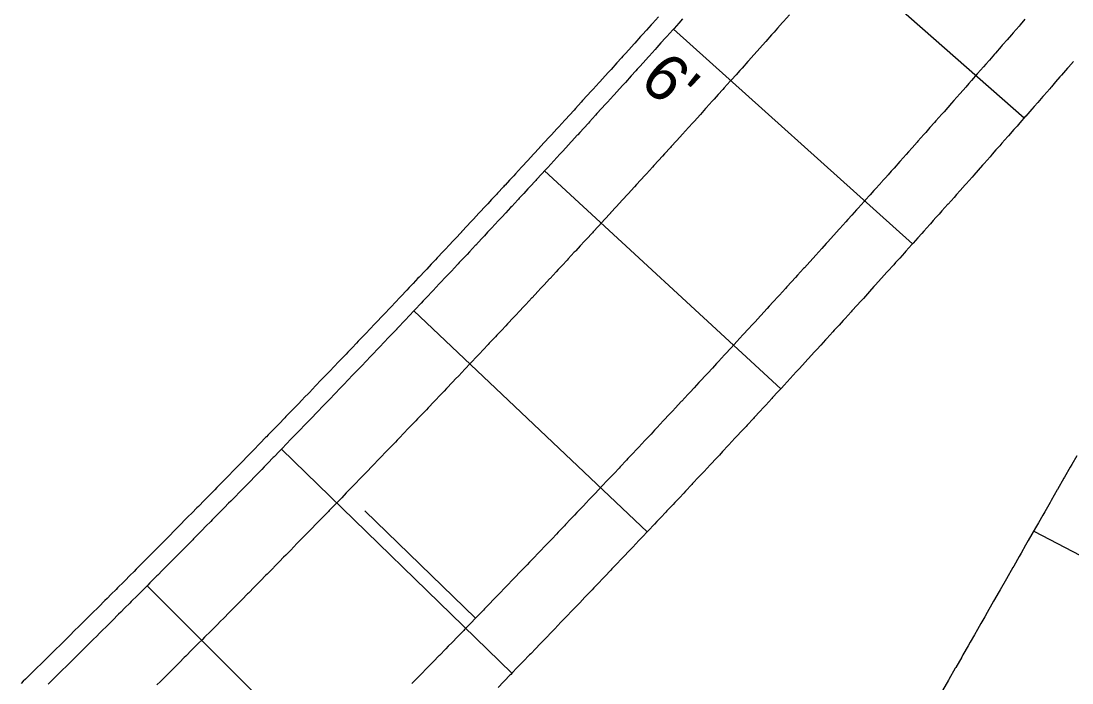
# Model space of a CAD drawing. Extents: x 2145147 to 2158018, y 137519 to 148068.
# Drawn here: x 2150345.5 to 2150427.2, y 143802 to 143853.5 of the extents above; entities that cross this region are included whole.
import ezdxf

# ---------------------------------------------------------------- set-up
doc = ezdxf.new("R2010")
doc.units = 0
for name, color, linetype in [('PR_Align_Ramp_F', 7, 'Continuous'), ('PR_Dimensions', 7, 'Continuous'), ('PR_Joint_Contraction', 7, 'Continuous'), ('PR_Joint_Long', 7, 'Continuous'), ('PR_Road_Concrete', 7, 'Continuous')]:
    doc.layers.add(name, color=color, linetype=linetype)

msp = doc.modelspace()

# ---------------------------------------------------------------- linework, layer by layer
at = {"layer": 'PR_Align_Ramp_F'}
msp.add_lwpolyline([(2150380.826, 143807.064), (2150372.211, 143815.417)], dxfattribs=at)
at = {"layer": 'PR_Joint_Contraction'}
for p, q in [((2150423.513, 143845.961), (2150402.719, 143864.212)), ((2150414.822, 143836.171), (2150396.222, 143852.871)), ((2150404.578, 143824.911), (2150386.198, 143841.852)), ((2150394.188, 143813.786), (2150376.032, 143830.966)), ((2150383.653, 143802.797), (2150365.723, 143820.214)), ((2150424.26, 143813.841), (2150452.174, 143799.313)), ((2150372.976, 143791.948), (2150355.275, 143809.598))]:
    msp.add_line(p, q, dxfattribs=at)
at = {"layer": 'PR_Joint_Long'}
for points in [[(2150405.248, 143853.979), (2150404.788, 143853.461), (2150404.726, 143853.391), (2150404.329, 143852.944), (2150404.062, 143852.644), (2150403.869, 143852.427), (2150403.408, 143851.91), (2150403.399, 143851.899), (2150402.948, 143851.394), (2150402.734, 143851.154), (2150402.487, 143850.877), (2150402.282, 143850.648), (2150402.069, 143850.41), (2150402.026, 143850.362), (2150401.564, 143849.846), (2150401.403, 143849.666), (2150401.102, 143849.331), (2150400.736, 143848.923), (2150400.64, 143848.816), (2150400.177, 143848.301), (2150400.069, 143848.18), (2150399.715, 143847.786), (2150399.401, 143847.438), (2150399.252, 143847.272), (2150398.788, 143846.758), (2150398.733, 143846.697), (2150398.324, 143846.244), (2150398.064, 143845.956), (2150397.86, 143845.731), (2150397.742, 143845.6), (2150397.396, 143845.218), (2150397.394, 143845.216), (2150396.931, 143844.705), (2150396.724, 143844.476), (2150396.466, 143844.193), (2150396.052, 143843.737), (2150396.001, 143843.681), (2150395.535, 143843.168), (2150395.381, 143842.999), (2150395.069, 143842.657), (2150394.708, 143842.261), (2150394.603, 143842.146), (2150394.136, 143841.634), (2150394.036, 143841.524), (2150393.67, 143841.123), (2150393.362, 143840.787), (2150393.202, 143840.613), (2150393.172, 143840.579), (2150392.735, 143840.102), (2150392.688, 143840.051), (2150392.267, 143839.593), (2150392.013, 143839.315), (2150391.799, 143839.083), (2150391.337, 143838.58), (2150391.331, 143838.574), (2150390.862, 143838.064), (2150390.661, 143837.846), (2150390.393, 143837.556), (2150389.984, 143837.112), (2150389.924, 143837.047), (2150389.454, 143836.538), (2150389.307, 143836.379), (2150388.984, 143836.031), (2150388.628, 143835.646), (2150388.571, 143835.585), (2150388.514, 143835.523), (2150388.043, 143835.015), (2150387.95, 143834.915), (2150387.572, 143834.508), (2150387.27, 143834.183), (2150387.101, 143834.002), (2150386.63, 143833.495), (2150386.59, 143833.452), (2150386.158, 143832.988), (2150385.91, 143832.722), (2150385.686, 143832.483), (2150385.228, 143831.992), (2150385.214, 143831.977), (2150384.741, 143831.471), (2150384.546, 143831.264), (2150384.268, 143830.966), (2150383.942, 143830.618), (2150383.864, 143830.535), (2150383.795, 143830.462), (2150383.321, 143829.957), (2150383.181, 143829.807), (2150382.847, 143829.453), (2150382.497, 143829.08), (2150382.373, 143828.949), (2150381.898, 143828.445), (2150381.812, 143828.353), (2150381.424, 143827.941), (2150381.127, 143827.627), (2150380.949, 143827.438), (2150380.473, 143826.935), (2150380.442, 143826.902), (2150379.997, 143826.433), (2150379.755, 143826.177), (2150379.521, 143825.93), (2150379.283, 143825.679), (2150379.068, 143825.453), (2150379.045, 143825.429), (2150378.568, 143824.927), (2150378.38, 143824.729), (2150378.091, 143824.425), (2150377.692, 143824.006), (2150377.614, 143823.924), (2150377.136, 143823.423), (2150377.003, 143823.284), (2150376.659, 143822.923), (2150376.313, 143822.562), (2150376.181, 143822.423), (2150375.702, 143821.922), (2150375.624, 143821.841), (2150375.223, 143821.423), (2150374.933, 143821.12), (2150374.744, 143820.924), (2150374.595, 143820.768), (2150374.265, 143820.424), (2150374.241, 143820.4), (2150373.785, 143819.926), (2150373.549, 143819.681), (2150373.305, 143819.427), (2150372.856, 143818.962), (2150372.825, 143818.929), (2150372.344, 143818.431), (2150372.163, 143818.244), (2150371.863, 143817.933), (2150371.469, 143817.526), (2150371.382, 143817.436), (2150370.9, 143816.939), (2150370.775, 143816.809), (2150370.419, 143816.442), (2150370.079, 143816.092), (2150369.937, 143815.946), (2150369.878, 143815.885), (2150369.454, 143815.449), (2150369.384, 143815.377), (2150368.972, 143814.953), (2150368.687, 143814.661), (2150368.489, 143814.458), (2150368.005, 143813.962), (2150367.99, 143813.947), (2150367.522, 143813.467), (2150367.292, 143813.233), (2150367.038, 143812.973), (2150366.594, 143812.519), (2150366.554, 143812.479), (2150366.117, 143812.033), (2150366.069, 143811.984), (2150365.895, 143811.807), (2150365.584, 143811.49), (2150365.196, 143811.095), (2150365.132, 143811.03), (2150365.1, 143810.997), (2150364.614, 143810.503), (2150364.496, 143810.383), (2150364.128, 143810.011), (2150363.795, 143809.672), (2150363.642, 143809.518), (2150363.156, 143809.025), (2150363.093, 143808.962), (2150362.669, 143808.533), (2150362.391, 143808.252), (2150362.183, 143808.042), (2150361.695, 143807.55), (2150361.689, 143807.543), (2150361.208, 143807.059), (2150360.985, 143806.835), (2150360.72, 143806.568), (2150360.357, 143806.202), (2150360.281, 143806.127), (2150360.232, 143806.078), (2150359.744, 143805.587), (2150359.577, 143805.42), (2150359.255, 143805.097), (2150358.872, 143804.713), (2150358.766, 143804.607), (2150358.277, 143804.118), (2150358.166, 143804.007), (2150357.787, 143803.629), (2150357.46, 143803.302), (2150357.298, 143803.14), (2150356.807, 143802.651), (2150356.753, 143802.597), (2150356.317, 143802.163), (2150356.045, 143801.893)], [(2150423.577, 143853.637), (2150423.198, 143853.201), (2150423.117, 143853.108), (2150422.659, 143852.581), (2150422.534, 143852.438), (2150422.198, 143852.052), (2150421.871, 143851.678), (2150421.819, 143851.619), (2150421.736, 143851.523), (2150421.277, 143850.998), (2150421.205, 143850.915), (2150420.816, 143850.47), (2150420.54, 143850.156), (2150420.353, 143849.942), (2150419.893, 143849.417), (2150419.873, 143849.394), (2150419.43, 143848.89), (2150419.207, 143848.636), (2150418.967, 143848.363), (2150418.541, 143847.879), (2150418.503, 143847.836), (2150418.042, 143847.313), (2150417.871, 143847.119), (2150417.578, 143846.787), (2150417.285, 143846.455), (2150417.203, 143846.362), (2150417.113, 143846.261), (2150416.651, 143845.738), (2150416.533, 143845.604), (2150416.186, 143845.213), (2150415.864, 143844.849), (2150415.72, 143844.687), (2150415.257, 143844.166), (2150415.192, 143844.092), (2150414.791, 143843.641), (2150414.521, 143843.338), (2150414.324, 143843.117), (2150413.86, 143842.596), (2150413.848, 143842.582), (2150413.393, 143842.072), (2150413.176, 143841.829), (2150412.926, 143841.549), (2150412.719, 143841.317), (2150412.503, 143841.076), (2150412.458, 143841.026), (2150411.993, 143840.506), (2150411.829, 143840.323), (2150411.524, 143839.983), (2150411.155, 143839.571), (2150411.056, 143839.461), (2150410.59, 143838.942), (2150410.478, 143838.818), (2150410.12, 143838.42), (2150409.803, 143838.068), (2150409.65, 143837.899), (2150409.183, 143837.381), (2150409.125, 143837.317), (2150408.713, 143836.86), (2150408.449, 143836.568), (2150408.243, 143836.34), (2150408.122, 143836.207), (2150407.774, 143835.821), (2150407.77, 143835.817), (2150407.303, 143835.302), (2150407.092, 143835.07), (2150406.832, 143834.782), (2150406.414, 143834.323), (2150406.36, 143834.263), (2150405.89, 143833.747), (2150405.733, 143833.574), (2150405.418, 143833.228), (2150405.053, 143832.828), (2150404.945, 143832.709), (2150404.475, 143832.194), (2150404.371, 143832.08), (2150404.001, 143831.676), (2150403.69, 143831.336), (2150403.529, 143831.159), (2150403.496, 143831.123), (2150403.056, 143830.644), (2150403.006, 143830.589), (2150402.582, 143830.127), (2150402.324, 143829.846), (2150402.107, 143829.61), (2150401.641, 143829.103), (2150401.632, 143829.093), (2150401.16, 143828.58), (2150400.955, 143828.358), (2150400.684, 143828.064), (2150400.271, 143827.616), (2150400.208, 143827.548), (2150399.735, 143827.036), (2150399.584, 143826.873), (2150399.258, 143826.521), (2150398.899, 143826.133), (2150398.841, 143826.07), (2150398.781, 143826.006), (2150398.307, 143825.494), (2150398.21, 143825.39), (2150397.83, 143824.98), (2150397.524, 143824.651), (2150397.352, 143824.466), (2150396.876, 143823.955), (2150396.834, 143823.91), (2150396.398, 143823.442), (2150396.146, 143823.172), (2150395.919, 143822.928), (2150395.458, 143822.434), (2150395.441, 143822.416), (2150394.964, 143821.906), (2150394.766, 143821.695), (2150394.484, 143821.394), (2150394.155, 143821.043), (2150394.075, 143820.958), (2150394.004, 143820.882), (2150393.527, 143820.373), (2150393.383, 143820.221), (2150393.046, 143819.862), (2150392.692, 143819.486), (2150392.565, 143819.351), (2150392.087, 143818.843), (2150391.998, 143818.749), (2150391.606, 143818.333), (2150391.305, 143818.015), (2150391.124, 143817.822), (2150390.644, 143817.315), (2150390.61, 143817.279), (2150390.162, 143816.806), (2150389.916, 143816.546), (2150389.68, 143816.297), (2150389.439, 143816.043), (2150389.221, 143815.814), (2150389.196, 143815.787), (2150388.716, 143815.282), (2150388.524, 143815.081), (2150388.232, 143814.773), (2150387.829, 143814.35), (2150387.748, 143814.265), (2150387.267, 143813.76), (2150387.13, 143813.617), (2150386.782, 143813.252), (2150386.433, 143812.888), (2150386.297, 143812.745), (2150385.815, 143812.241), (2150385.733, 143812.156), (2150385.329, 143811.734), (2150385.035, 143811.428), (2150384.844, 143811.229), (2150384.693, 143811.071), (2150384.36, 143810.724), (2150384.334, 143810.697), (2150383.874, 143810.219), (2150383.634, 143809.97), (2150383.387, 143809.713), (2150382.934, 143809.244), (2150382.9, 143809.208), (2150382.416, 143808.706), (2150382.231, 143808.515), (2150381.928, 143808.202), (2150381.53, 143807.79), (2150381.44, 143807.697), (2150380.954, 143807.196), (2150380.825, 143807.063), (2150380.466, 143806.692), (2150380.123, 143806.339), (2150379.978, 143806.19), (2150379.917, 143806.127), (2150379.49, 143805.688), (2150379.417, 143805.613), (2150379.001, 143805.186), (2150378.713, 143804.89), (2150378.511, 143804.683), (2150378.024, 143804.184), (2150378.006, 143804.165), (2150377.534, 143803.682), (2150377.301, 143803.444), (2150377.043, 143803.18), (2150376.595, 143802.723), (2150376.552, 143802.679), (2150376.113, 143802.23), (2150376.063, 143802.18), (2150375.887, 143802)]]:
    msp.add_lwpolyline(points, dxfattribs=at)
at = {"layer": 'PR_Road_Concrete'}
for points in [[(2150395.057, 143853.829), (2150394.597, 143853.317), (2150394.49, 143853.198), (2150394.138, 143852.806), (2150393.826, 143852.46), (2150393.678, 143852.295), (2150393.217, 143851.785), (2150393.162, 143851.724), (2150392.756, 143851.274), (2150392.498, 143850.988), (2150392.295, 143850.764), (2150392.178, 143850.634), (2150391.834, 143850.255), (2150391.832, 143850.253), (2150391.372, 143849.745), (2150391.166, 143849.518), (2150390.911, 143849.236), (2150390.5, 143848.784), (2150390.448, 143848.727), (2150389.986, 143848.219), (2150389.832, 143848.05), (2150389.523, 143847.71), (2150389.164, 143847.317), (2150389.06, 143847.202), (2150388.596, 143846.694), (2150388.496, 143846.585), (2150388.132, 143846.187), (2150387.827, 143845.853), (2150387.668, 143845.68), (2150387.637, 143845.646), (2150387.204, 143845.173), (2150387.157, 143845.121), (2150386.739, 143844.666), (2150386.486, 143844.391), (2150386.274, 143844.16), (2150385.815, 143843.661), (2150385.809, 143843.654), (2150385.343, 143843.148), (2150385.143, 143842.931), (2150384.877, 143842.642), (2150384.471, 143842.202), (2150384.411, 143842.137), (2150383.945, 143841.632), (2150383.798, 143841.474), (2150383.478, 143841.128), (2150383.124, 143840.746), (2150383.068, 143840.685), (2150383.011, 143840.623), (2150382.543, 143840.119), (2150382.45, 143840.019), (2150382.075, 143839.615), (2150381.775, 143839.292), (2150381.607, 143839.112), (2150381.139, 143838.608), (2150381.099, 143838.566), (2150380.67, 143838.105), (2150380.423, 143837.841), (2150380.201, 143837.603), (2150379.746, 143837.116), (2150379.732, 143837.1), (2150379.262, 143836.598), (2150379.069, 143836.392), (2150378.792, 143836.096), (2150378.469, 143835.751), (2150378.391, 143835.668), (2150378.322, 143835.595), (2150377.852, 143835.094), (2150377.712, 143834.945), (2150377.381, 143834.593), (2150377.033, 143834.222), (2150376.91, 143834.092), (2150376.438, 143833.591), (2150376.353, 143833.501), (2150375.967, 143833.091), (2150375.672, 143832.779), (2150375.495, 143832.591), (2150375.022, 143832.092), (2150374.991, 143832.059), (2150374.55, 143831.593), (2150374.309, 143831.339), (2150374.077, 143831.094), (2150373.84, 143830.844), (2150373.626, 143830.619), (2150373.604, 143830.595), (2150373.13, 143830.097), (2150372.943, 143829.9), (2150372.656, 143829.598), (2150372.26, 143829.182), (2150372.182, 143829.101), (2150371.708, 143828.603), (2150371.575, 143828.464), (2150371.233, 143828.106), (2150370.89, 143827.747), (2150370.758, 143827.609), (2150370.283, 143827.112), (2150370.205, 143827.031), (2150369.807, 143826.616), (2150369.518, 143826.315), (2150369.331, 143826.12), (2150369.183, 143825.965), (2150368.855, 143825.624), (2150368.831, 143825.599), (2150368.378, 143825.128), (2150368.144, 143824.885), (2150367.901, 143824.633), (2150367.456, 143824.171), (2150367.424, 143824.138), (2150366.947, 143823.643), (2150366.767, 143823.457), (2150366.469, 143823.149), (2150366.078, 143822.744), (2150365.991, 143822.655), (2150365.513, 143822.161), (2150365.388, 143822.032), (2150365.034, 143821.667), (2150364.697, 143821.32), (2150364.555, 143821.174), (2150364.497, 143821.114), (2150364.076, 143820.681), (2150364.006, 143820.609), (2150363.596, 143820.189), (2150363.314, 143819.899), (2150363.117, 143819.696), (2150362.637, 143819.204), (2150362.621, 143819.189), (2150362.156, 143818.712), (2150361.928, 143818.479), (2150361.675, 143818.221), (2150361.235, 143817.771), (2150361.194, 143817.73), (2150360.761, 143817.287), (2150360.713, 143817.239), (2150360.54, 143817.063), (2150360.231, 143816.748), (2150359.845, 143816.355), (2150359.782, 143816.29), (2150359.75, 143816.258), (2150359.267, 143815.768), (2150359.15, 143815.648), (2150358.785, 143815.278), (2150358.453, 143814.942), (2150358.302, 143814.789), (2150357.819, 143814.3), (2150357.757, 143814.236), (2150357.336, 143813.811), (2150357.059, 143813.531), (2150356.852, 143813.322), (2150356.368, 143812.834), (2150356.361, 143812.827), (2150355.884, 143812.346), (2150355.662, 143812.123), (2150355.399, 143811.858), (2150355.038, 143811.495), (2150354.963, 143811.42), (2150354.914, 143811.371), (2150354.429, 143810.884), (2150354.263, 143810.717), (2150353.944, 143810.397), (2150353.563, 143810.015), (2150353.458, 143809.91), (2150352.972, 143809.424), (2150352.862, 143809.314), (2150352.486, 143808.938), (2150352.16, 143808.613), (2150351.999, 143808.453), (2150351.512, 143807.967), (2150351.458, 143807.913), (2150351.025, 143807.482), (2150350.755, 143807.214), (2150350.537, 143806.997), (2150350.266, 143806.728), (2150350.051, 143806.515), (2150350.05, 143806.513), (2150349.561, 143806.029), (2150349.347, 143805.816), (2150349.073, 143805.545), (2150348.642, 143805.119), (2150348.584, 143805.061), (2150348.095, 143804.578), (2150347.937, 143804.422), (2150347.606, 143804.095), (2150347.231, 143803.725), (2150347.117, 143803.612), (2150346.627, 143803.13), (2150346.524, 143803.029), (2150346.137, 143802.648), (2150345.817, 143802.334), (2150345.646, 143802.166), (2150345.466, 143801.989)], [(2150396.937, 143853.668), (2150396.638, 143853.334), (2150396.274, 143852.929), (2150396.178, 143852.822), (2150395.718, 143852.31), (2150395.61, 143852.19), (2150395.258, 143851.798), (2150394.946, 143851.452), (2150394.797, 143851.287), (2150394.336, 143850.775), (2150394.281, 143850.715), (2150393.874, 143850.264), (2150393.615, 143849.978), (2150393.413, 143849.754), (2150393.295, 143849.623), (2150392.951, 143849.243), (2150392.949, 143849.241), (2150392.489, 143848.733), (2150392.282, 143848.506), (2150392.026, 143848.223), (2150391.615, 143847.77), (2150391.563, 143847.714), (2150391.1, 143847.205), (2150390.946, 143847.036), (2150390.637, 143846.696), (2150390.278, 143846.302), (2150390.173, 143846.187), (2150389.709, 143845.678), (2150389.608, 143845.568), (2150389.244, 143845.17), (2150388.938, 143844.835), (2150388.78, 143844.662), (2150388.749, 143844.629), (2150388.315, 143844.155), (2150388.267, 143844.103), (2150387.849, 143843.647), (2150387.596, 143843.372), (2150387.384, 143843.14), (2150386.924, 143842.64), (2150386.918, 143842.634), (2150386.451, 143842.127), (2150386.251, 143841.91), (2150385.985, 143841.621), (2150385.578, 143841.18), (2150385.518, 143841.115), (2150385.051, 143840.609), (2150384.904, 143840.451), (2150384.583, 143840.104), (2150384.229, 143839.722), (2150384.173, 143839.661), (2150384.116, 143839.599), (2150383.648, 143839.094), (2150383.554, 143838.994), (2150383.179, 143838.59), (2150382.878, 143838.266), (2150382.71, 143838.086), (2150382.241, 143837.582), (2150382.202, 143837.539), (2150381.772, 143837.078), (2150381.525, 143836.813), (2150381.303, 143836.575), (2150380.847, 143836.087), (2150380.833, 143836.072), (2150380.362, 143835.569), (2150380.169, 143835.362), (2150379.892, 143835.066), (2150379.568, 143834.72), (2150379.49, 143834.637), (2150379.421, 143834.564), (2150378.95, 143834.062), (2150378.81, 143833.913), (2150378.479, 143833.56), (2150378.13, 143833.19), (2150378.007, 143833.059), (2150377.535, 143832.558), (2150377.449, 143832.467), (2150377.062, 143832.057), (2150376.767, 143831.745), (2150376.59, 143831.557), (2150376.117, 143831.056), (2150376.085, 143831.023), (2150375.644, 143830.557), (2150375.403, 143830.302), (2150375.17, 143830.057), (2150374.933, 143829.807), (2150374.719, 143829.582), (2150374.696, 143829.558), (2150374.222, 143829.058), (2150374.035, 143828.862), (2150373.748, 143828.56), (2150373.35, 143828.143), (2150373.273, 143828.061), (2150372.798, 143827.563), (2150372.665, 143827.424), (2150372.322, 143827.065), (2150371.979, 143826.706), (2150371.847, 143826.567), (2150371.371, 143826.07), (2150371.293, 143825.988), (2150370.894, 143825.573), (2150370.605, 143825.272), (2150370.418, 143825.076), (2150370.27, 143824.922), (2150369.941, 143824.58), (2150369.918, 143824.555), (2150369.464, 143824.084), (2150369.229, 143823.84), (2150368.986, 143823.588), (2150368.54, 143823.125), (2150368.509, 143823.092), (2150368.031, 143822.597), (2150367.851, 143822.41), (2150367.552, 143822.102), (2150367.16, 143821.696), (2150367.074, 143821.607), (2150366.595, 143821.112), (2150366.469, 143820.983), (2150366.115, 143820.618), (2150365.778, 143820.27), (2150365.636, 143820.124), (2150365.577, 143820.064), (2150365.156, 143819.631), (2150365.086, 143819.558), (2150364.676, 143819.137), (2150364.393, 143818.847), (2150364.195, 143818.644), (2150363.715, 143818.152), (2150363.699, 143818.136), (2150363.234, 143817.659), (2150363.005, 143817.426), (2150362.752, 143817.167), (2150362.311, 143816.716), (2150362.271, 143816.675), (2150361.836, 143816.232), (2150361.789, 143816.184), (2150361.615, 143816.007), (2150361.306, 143815.692), (2150360.92, 143815.299), (2150360.856, 143815.234), (2150360.824, 143815.201), (2150360.341, 143814.711), (2150360.223, 143814.591), (2150359.858, 143814.22), (2150359.526, 143813.884), (2150359.374, 143813.73), (2150358.891, 143813.241), (2150358.828, 143813.177), (2150358.407, 143812.751), (2150358.13, 143812.471), (2150357.922, 143812.262), (2150357.438, 143811.773), (2150357.431, 143811.766), (2150356.953, 143811.284), (2150356.731, 143811.061), (2150356.468, 143810.796), (2150356.106, 143810.432), (2150356.031, 143810.357), (2150355.982, 143810.308), (2150355.496, 143809.82), (2150355.33, 143809.654), (2150355.01, 143809.333), (2150354.629, 143808.951), (2150354.524, 143808.845), (2150354.037, 143808.359), (2150353.927, 143808.248), (2150353.55, 143807.872), (2150353.224, 143807.547), (2150353.063, 143807.386), (2150352.575, 143806.9), (2150352.521, 143806.846), (2150352.087, 143806.414), (2150351.817, 143806.145), (2150351.599, 143805.929), (2150351.328, 143805.659), (2150351.113, 143805.445), (2150351.111, 143805.444), (2150350.622, 143804.959), (2150350.407, 143804.746), (2150350.133, 143804.474), (2150349.702, 143804.047), (2150349.644, 143803.99), (2150349.154, 143803.506), (2150348.995, 143803.349), (2150348.664, 143803.023), (2150348.289, 143802.652), (2150348.174, 143802.539), (2150347.684, 143802.056), (2150347.581, 143801.955)], [(2150427.352, 143850.358), (2150426.97, 143849.919), (2150426.89, 143849.827), (2150426.428, 143849.297), (2150426.304, 143849.154), (2150425.966, 143848.766), (2150425.637, 143848.389), (2150425.586, 143848.331), (2150425.504, 143848.236), (2150425.041, 143847.706), (2150424.969, 143847.625), (2150424.578, 143847.177), (2150424.301, 143846.861), (2150424.114, 143846.647), (2150423.65, 143846.119), (2150423.632, 143846.098), (2150423.186, 143845.59), (2150422.963, 143845.335), (2150422.722, 143845.061), (2150422.292, 143844.573), (2150422.257, 143844.533), (2150421.792, 143844.005), (2150421.621, 143843.812), (2150421.326, 143843.478), (2150421.032, 143843.144), (2150420.95, 143843.051), (2150420.861, 143842.951), (2150420.395, 143842.424), (2150420.277, 143842.291), (2150419.928, 143841.897), (2150419.604, 143841.531), (2150419.462, 143841.37), (2150418.995, 143840.844), (2150418.931, 143840.772), (2150418.527, 143840.318), (2150418.256, 143840.014), (2150418.06, 143839.793), (2150417.592, 143839.267), (2150417.581, 143839.256), (2150417.123, 143838.742), (2150416.906, 143838.499), (2150416.655, 143838.218), (2150416.446, 143837.985), (2150416.23, 143837.742), (2150416.186, 143837.693), (2150415.717, 143837.169), (2150415.553, 143836.986), (2150415.247, 143836.645), (2150414.875, 143836.231), (2150414.777, 143836.122), (2150414.307, 143835.598), (2150414.197, 143835.476), (2150413.836, 143835.075), (2150413.518, 143834.721), (2150413.366, 143834.552), (2150412.894, 143834.03), (2150412.838, 143833.968), (2150412.423, 143833.508), (2150412.158, 143833.215), (2150411.951, 143832.986), (2150411.831, 143832.853), (2150411.479, 143832.464), (2150411.477, 143832.462), (2150411.007, 143831.943), (2150410.796, 143831.71), (2150410.534, 143831.422), (2150410.113, 143830.959), (2150410.061, 143830.901), (2150409.588, 143830.381), (2150409.431, 143830.208), (2150409.114, 143829.86), (2150408.747, 143829.458), (2150408.64, 143829.341), (2150408.166, 143828.821), (2150408.063, 143828.708), (2150407.691, 143828.302), (2150407.378, 143827.959), (2150407.216, 143827.783), (2150407.185, 143827.748), (2150406.741, 143827.264), (2150406.693, 143827.211), (2150406.265, 143826.745), (2150406.007, 143826.463), (2150405.79, 143826.227), (2150405.32, 143825.716), (2150405.313, 143825.709), (2150404.837, 143825.192), (2150404.632, 143824.97), (2150404.36, 143824.674), (2150403.944, 143824.224), (2150403.883, 143824.157), (2150403.406, 143823.641), (2150403.255, 143823.478), (2150402.928, 143823.124), (2150402.566, 143822.734), (2150402.508, 143822.671), (2150402.45, 143822.608), (2150401.971, 143822.092), (2150401.876, 143821.99), (2150401.493, 143821.577), (2150401.185, 143821.246), (2150401.014, 143821.061), (2150400.534, 143820.546), (2150400.494, 143820.503), (2150400.055, 143820.032), (2150399.802, 143819.761), (2150399.575, 143819.517), (2150399.109, 143819.019), (2150399.095, 143819.003), (2150398.614, 143818.489), (2150398.416, 143818.278), (2150398.133, 143817.976), (2150397.802, 143817.622), (2150397.722, 143817.537), (2150397.652, 143817.462), (2150397.171, 143816.949), (2150397.028, 143816.797), (2150396.689, 143816.437), (2150396.333, 143816.058), (2150396.207, 143815.924), (2150395.724, 143815.412), (2150395.637, 143815.319), (2150395.242, 143814.901), (2150394.94, 143814.581), (2150394.759, 143814.389), (2150394.275, 143813.878), (2150394.243, 143813.844), (2150393.792, 143813.367), (2150393.545, 143813.107), (2150393.308, 143812.856), (2150393.066, 143812.601), (2150392.847, 143812.371), (2150392.823, 143812.346), (2150392.339, 143811.836), (2150392.148, 143811.635), (2150391.854, 143811.326), (2150391.448, 143810.9), (2150391.369, 143810.817), (2150390.883, 143810.308), (2150390.748, 143810.166), (2150390.397, 143809.799), (2150390.047, 143809.432), (2150389.911, 143809.29), (2150389.425, 143808.782), (2150389.345, 143808.698), (2150388.938, 143808.274), (2150388.643, 143807.966), (2150388.451, 143807.766), (2150388.299, 143807.608), (2150387.964, 143807.259), (2150387.94, 143807.234), (2150387.476, 143806.752), (2150387.236, 143806.503), (2150386.988, 143806.245), (2150386.532, 143805.772), (2150386.5, 143805.738), (2150386.011, 143805.232), (2150385.827, 143805.042), (2150385.523, 143804.726), (2150385.122, 143804.312), (2150385.033, 143804.221), (2150384.544, 143803.715), (2150384.416, 143803.583), (2150384.054, 143803.21), (2150383.709, 143802.855), (2150383.564, 143802.706), (2150383.504, 143802.644), (2150383.074, 143802.201), (2150383.002, 143802.127), (2150382.583, 143801.697)], [(2150427.607, 143819.689), (2150427.228, 143819.027), (2150427.11, 143818.82), (2150426.663, 143818.04), (2150426.613, 143817.952), (2150426.116, 143817.083), (2150426.098, 143817.053), (2150425.618, 143816.215), (2150425.533, 143816.066), (2150425.121, 143815.346), (2150424.969, 143815.079), (2150424.624, 143814.478), (2150424.404, 143814.092), (2150424.127, 143813.609), (2150423.839, 143813.105), (2150423.63, 143812.74), (2150423.274, 143812.118), (2150423.133, 143811.872), (2150422.709, 143811.131), (2150422.636, 143811.003), (2150422.144, 143810.144), (2150422.138, 143810.135), (2150421.641, 143809.266), (2150421.579, 143809.157), (2150421.144, 143808.397), (2150421.014, 143808.17), (2150420.647, 143807.529), (2150420.449, 143807.183), (2150420.15, 143806.66), (2150419.884, 143806.196), (2150419.653, 143805.792), (2150419.319, 143805.209), (2150419.155, 143804.923), (2150418.754, 143804.222), (2150418.658, 143804.055), (2150418.189, 143803.235), (2150418.161, 143803.186), (2150417.664, 143802.317), (2150417.624, 143802.248), (2150417.167, 143801.449)]]:
    msp.add_lwpolyline(points, dxfattribs=at)

# ---------------------------------------------------------------- texts
at = {"layer": 'PR_Dimensions'}
msp.add_text("6'", height=3.6, rotation=319.1685, dxfattribs=at).set_placement((2150393.459, 143848.647))

doc.saveas('drawing.dxf')
